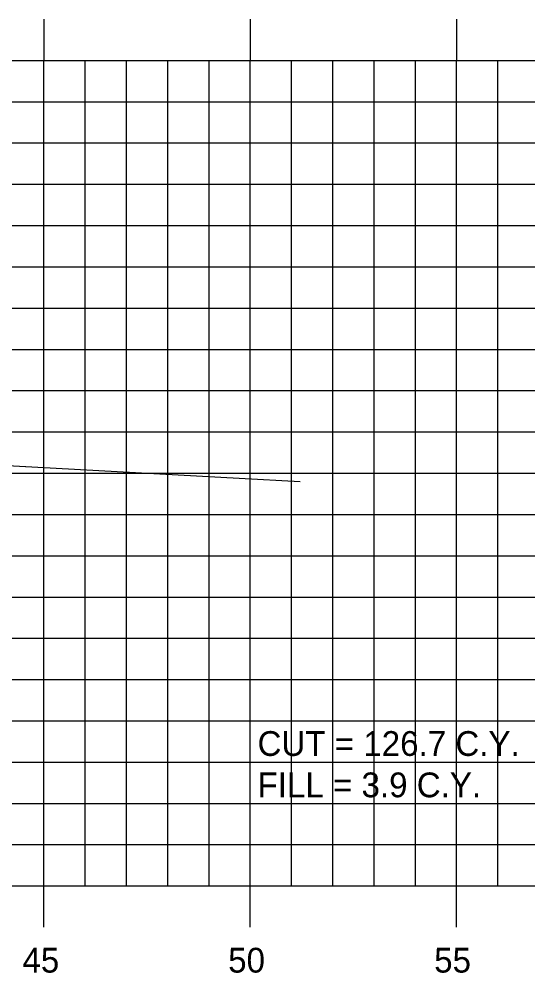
# Model space of a CAD drawing. Extents: x 859129 to 859299, y 366268 to 366378.
# Drawn here: x 859256.86 to 859269.19, y 366335.13 to 366358.24 of the extents above; entities that cross this region are included whole.
import ezdxf

# ---------------------------------------------------------------- set-up
doc = ezdxf.new("R2010")
doc.units = 0
for name, color, linetype in [('ANNOTATION', 7, 'Continuous'), ('H_V ANNOTATION', 7, 'Continuous'), ('MAJOR', 7, 'Continuous'), ('MINOR', 7, 'Continuous'), ('S_Roadway_Centerline', 7, 'Continuous')]:
    doc.layers.add(name, color=color, linetype=linetype)

msp = doc.modelspace()

# ---------------------------------------------------------------- linework, layer by layer
at = {"layer": 'MAJOR'}
for p, q in [((859257.462, 366358.238), (859257.462, 366357.236)), ((859262.462, 366358.238), (859262.462, 366357.236)), ((859267.462, 366358.238), (859267.462, 366357.236)), ((859142.462, 366357.236), (859282.462, 366357.236)), ((859142.462, 366357.236), (859282.462, 366357.236)), ((859257.462, 366337.236), (859257.462, 366357.236)), ((859262.462, 366337.236), (859262.462, 366357.236)), ((859267.462, 366337.236), (859267.462, 366357.236)), ((859142.462, 366352.236), (859282.462, 366352.236)), ((859142.462, 366347.236), (859282.462, 366347.236)), ((859142.462, 366342.236), (859282.462, 366342.236)), ((859142.462, 366337.236), (859282.462, 366337.236)), ((859142.462, 366337.236), (859282.462, 366337.236)), ((859257.462, 366336.234), (859257.462, 366337.236)), ((859262.462, 366336.234), (859262.462, 366337.236)), ((859267.462, 366336.234), (859267.462, 366337.236))]:
    msp.add_line(p, q, dxfattribs=at)
at = {"layer": 'MINOR'}
for p, q in [((859258.462, 366337.236), (859258.462, 366357.236)), ((859259.462, 366337.236), (859259.462, 366357.236)), ((859260.462, 366337.236), (859260.462, 366357.236)), ((859261.462, 366337.236), (859261.462, 366357.236)), ((859263.462, 366337.236), (859263.462, 366357.236)), ((859264.462, 366337.236), (859264.462, 366357.236)), ((859265.462, 366337.236), (859265.462, 366357.236)), ((859266.462, 366337.236), (859266.462, 366357.236)), ((859268.462, 366337.236), (859268.462, 366357.236)), ((859142.462, 366356.236), (859282.462, 366356.236)), ((859142.462, 366355.236), (859282.462, 366355.236)), ((859142.462, 366354.236), (859282.462, 366354.236)), ((859142.462, 366353.236), (859282.462, 366353.236)), ((859142.462, 366351.236), (859282.462, 366351.236)), ((859142.462, 366350.236), (859282.462, 366350.236)), ((859142.462, 366349.236), (859282.462, 366349.236)), ((859142.462, 366348.236), (859282.462, 366348.236)), ((859142.462, 366346.236), (859282.462, 366346.236)), ((859142.462, 366345.236), (859282.462, 366345.236)), ((859142.462, 366344.236), (859282.462, 366344.236)), ((859142.462, 366343.236), (859282.462, 366343.236)), ((859142.462, 366341.236), (859282.462, 366341.236)), ((859142.462, 366340.236), (859282.462, 366340.236)), ((859142.462, 366339.236), (859282.462, 366339.236)), ((859142.462, 366338.236), (859282.462, 366338.236))]:
    msp.add_line(p, q, dxfattribs=at)
at = {"layer": 'S_Roadway_Centerline'}
msp.add_lwpolyline([(859229.051, 366348.623), (859249.622, 366347.669), (859251.895, 366347.658), (859253.318, 366347.598), (859263.668, 366347.033)], dxfattribs=at)

# ---------------------------------------------------------------- texts
at = {"layer": 'ANNOTATION'}
for s, p in [('CUT = 126.7 C.Y.', (859262.638, 366340.386)), ('FILL = 3.9 C.Y.', (859262.638, 366339.384))]:
    msp.add_text(s, height=0.6, dxfattribs=at).set_placement(p)
at = {"layer": 'H_V ANNOTATION'}
for s, p in [('45', (859256.94, 366335.136)), ('50', (859261.926, 366335.136)), ('55', (859266.918, 366335.136))]:
    msp.add_text(s, height=0.6, dxfattribs=at).set_placement(p)

doc.saveas('drawing.dxf')
